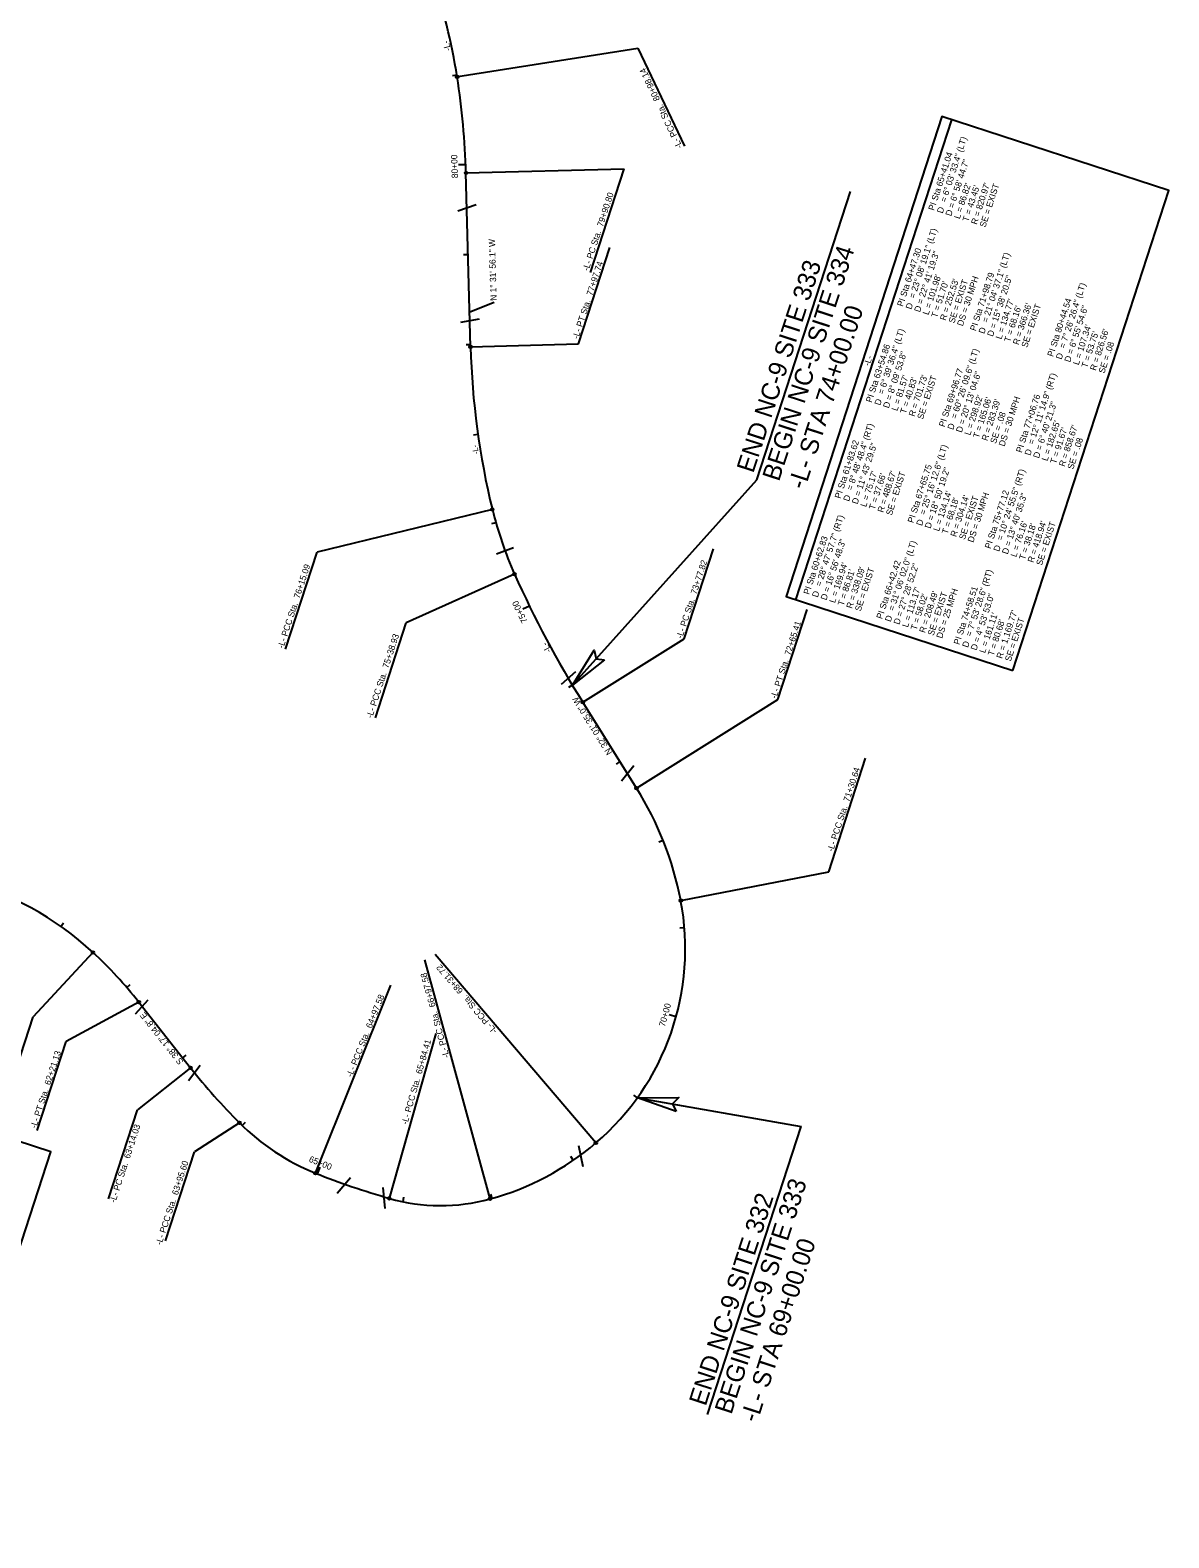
# Model space of a CAD drawing. Extents: x 1019959 to 1023888, y 635993 to 644996.
# Drawn here: x 1022623 to 1023888, y 639454 to 641128 of the extents above; entities that cross this region are included whole.
import ezdxf

# ---------------------------------------------------------------- set-up
doc = ezdxf.new("R2010")
doc.units = 0
for name, color, linetype in [('Cogo Default Point CELL', 7, 'Continuous'), ('COGO Default Point Elevation', 7, 'Continuous'), ('COGO Default Point Number', 7, 'Continuous'), ('Exist Other Culture Well CELL', 7, 'Continuous'), ('Exist Roads EOT', 7, 'Continuous'), ('Exist Structure Minor Pipes CMP 18 Inch Cogo Comment', 7, 'Continuous'), ('Exist Structure Minor Pipes CMP 18 Inch Cogo Number', 7, 'Continuous'), ('Exist Structure Minor Pipes CMP 24 Inch Cogo Number', 7, 'Continuous'), ('Exist Utilities Power Pole CELL', 7, 'Continuous'), ('Exist Utilities Power Pole Cogo Elevation', 7, 'Continuous'), ('Exist Utilities Power Pole Cogo Number', 7, 'Continuous')]:
    doc.layers.add(name, color=color, linetype=linetype)

msp = doc.modelspace()

# ---------------------------------------------------------------- linework, layer by layer
at = {"layer": 'COGO Default Point Elevation'}
for p, q in [((1023097.3, 641078.5), (1023092.3, 641077.7)), ((1023109.8, 640879), (1023104.8, 640878.9)), ((1023112.5, 640779.1), (1023107.5, 640778.9)), ((1023120.7, 640679.5), (1023115.7, 640678.8)), ((1023140.6, 640581.5), (1023135.8, 640580.2)), ((1023225.6, 640401.1), (1023221.3, 640398.5)), ((1023278.4, 640316.2), (1023274.2, 640313.5)), ((1023326.3, 640228.6), (1023321.7, 640226.7)), ((1022657.4, 640133.2), (1022660.3, 640137.3)), ((1023350.1, 640131.8), (1023345.1, 640131.4)), ((1022730.6, 640065.4), (1022734.4, 640068.7)), ((1022792.9, 639987.2), (1022796.8, 639990.3)), ((1023297.8, 639943), (1023293.8, 639945.9)), ((1022858.9, 639912.1), (1022862.4, 639915.7)), ((1023226.6, 639873.6), (1023223.8, 639877.7)), ((1023037.5, 639827.6), (1023038.5, 639832.5)), ((1023136.5, 639831.3), (1023135.1, 639836.1))]:
    msp.add_line(p, q, dxfattribs=at)
at = {"layer": 'COGO Default Point Number'}
for p, q in [((1023107.1, 640979), (1023099.1, 640978.7)), ((1023177.9, 640488.9), (1023170.7, 640485.4)), ((1023340.8, 640032.8), (1023333.1, 640034.9)), ((1022942.5, 639858.4), (1022945.4, 639865.9))]:
    msp.add_line(p, q, dxfattribs=at)
at = {"layer": 'Exist Other Culture Well CELL'}
for p, q in [((1023430.3, 640629.2), (1023534.3, 640949.2)), ((1023225.6, 640401.1), (1023430.3, 640629.2)), ((1023297.8, 639943), (1023479.7, 639911.2)), ((1023375.7, 639591.2), (1023479.7, 639911.2))]:
    msp.add_line(p, q, dxfattribs=at)
at = {"layer": 'Exist Roads EOT'}
for p, q in [((1023096.1, 641076.4), (1023298.4, 641108.3)), ((1023298.4, 641108.3), (1023350, 640999.5)), ((1023107.4, 640969.8), (1023283.1, 640974.5)), ((1023245.6, 640859.1), (1023283.1, 640974.5)), ((1023232.3, 640780), (1023267.1, 640886.9)), ((1023112.5, 640776.8), (1023232.3, 640780)), ((1023136.7, 640596.1), (1022942.1, 640548.6)), ((1022907.1, 640441), (1022942.1, 640548.6)), ((1023349.8, 640452.6), (1023382.2, 640552.4)), ((1023161.4, 640524.2), (1023041, 640470.3)), ((1023453.8, 640385), (1023486.3, 640485.1)), ((1023006.8, 640364.9), (1023041, 640470.3)), ((1023237.2, 640382.1), (1023349.8, 640452.6)), ((1023296.8, 640286.8), (1023453.8, 640385)), ((1023510.3, 640194), (1023551.2, 640319.9)), ((1023345.9, 640162.1), (1023510.3, 640194)), ((1022693.1, 640104.3), (1022626.6, 640032.7)), ((1023134.1, 639830.7), (1023061.8, 640096)), ((1023251.7, 639892.9), (1023073.1, 640101.9)), ((1022940.2, 639859.3), (1023024.1, 640067.9)), ((1022744.1, 640049.1), (1022663.3, 640005.5)), ((1022594.8, 639934.8), (1022626.6, 640032.7)), ((1023022.3, 639831.3), (1023074.3, 640014.3)), ((1022631.2, 639906.7), (1022663.3, 640005.5)), ((1022801.6, 639976.2), (1022742.5, 639929.5)), ((1022710.3, 639830.6), (1022742.5, 639929.5)), ((1022855.8, 639915.2), (1022806, 639882.8)), ((1022773.8, 639784), (1022806, 639882.8))]:
    msp.add_line(p, q, dxfattribs=at)
for centre in [(1023097.5, 641076.6), (1023107.4, 640969.8), (1023112.5, 640776.8), (1023136.7, 640596.1), (1023161.4, 640524.2), (1023237.2, 640382.1), (1023296.8, 640286.8), (1023345.9, 640162.1), (1022693.1, 640104.3), (1022744.1, 640049.1), (1022801.6, 639976.2), (1022855.8, 639915.2), (1023251.7, 639892.9), (1022940.2, 639859.3), (1023022.3, 639831.3), (1023134.1, 639830.7)]:
    msp.add_circle(centre, 1.5, dxfattribs=at)
at = {"layer": 'Exist Structure Minor Pipes CMP 18 Inch Cogo Comment'}
for points in [[(1023261.4, 640429.4), (1023225.6, 640401.1), (1023249.9, 640440.1), (1023252, 640430.5)], [(1023340.8, 639927.6), (1023297.8, 639943), (1023343.8, 639943.1), (1023336.7, 639936.2)]]:
    msp.add_lwpolyline(points, close=True, dxfattribs=at)
at = {"layer": 'Exist Structure Minor Pipes CMP 18 Inch Cogo Number'}
for p, q in [((1023112.5, 640776.8), (1023107.4, 640969.8)), ((1023296.8, 640286.8), (1023237.2, 640382.1)), ((1022744.1, 640049.1), (1022801.6, 639976.2))]:
    msp.add_line(p, q, dxfattribs=at)
for centre, radius, start, end in [((1022417.8, 640969.3), 688.2, 8.9729, 18.6571), ((1022281.1, 640947.7), 826.6, 1.5322, 8.9729), ((1023970.9, 640799.8), 858.7, 181.5322, 193.7197), ((1023543.7, 640695.5), 418.9, 193.7197, 204.1351), ((1024228.9, 641002.5), 1169.8, 204.1351, 212.0264), ((1022986.2, 640092.6), 366.4, 10.9494, 32.0264), ((1022463, 639856.6), 338.1, 47.0981, 75.8975), ((1023067.6, 640108.3), 283.4, 310.5134, 10.9494), ((1022360.5, 639746.3), 488.7, 38.2847, 47.0981), ((1023352.4, 640410.9), 701.7, 218.2847, 224.9448), ((1023034.5, 640093.6), 252.5, 224.9448, 248.0834), ((1023054.2, 640124.1), 304.1, 285.2433, 310.5134), ((1023246.7, 640621), 821, 248.0834, 254.1427), ((1023079.3, 640031.8), 208.5, 254.1427, 285.2433)]:
    msp.add_arc(centre, radius, start, end, dxfattribs=at)
at = {"layer": 'Exist Structure Minor Pipes CMP 24 Inch Cogo Number'}
for p, q in [((1023098.3, 640927.7), (1023118.8, 640934.7)), ((1023101.6, 640804.3), (1023122.6, 640807.9)), ((1023141.3, 640546.8), (1023160.3, 640553.8)), ((1023229.1, 640415.8), (1023213.2, 640401.8)), ((1023280.3, 640294.7), (1023293.9, 640311.8)), ((1022740.4, 640036.3), (1022754.4, 640051.8)), ((1022812.2, 639978.7), (1022799.2, 639961.6)), ((1023232.3, 639889.9), (1023237.3, 639866.7)), ((1022979.3, 639854.2), (1022964.3, 639836.7)), ((1023015.2, 639843.2), (1023017.3, 639820.1))]:
    msp.add_line(p, q, dxfattribs=at)
at = {"layer": 'Exist Utilities Power Pole CELL'}
for p, q in [((1023112.5, 640776.8), (1023107.4, 640969.8)), ((1023296.8, 640286.8), (1023237.2, 640382.1)), ((1022744.1, 640049.1), (1022801.6, 639976.2))]:
    msp.add_line(p, q, dxfattribs=at)
for centre, radius, start, end in [((1022417.8, 640969.3), 688.2, 8.9729, 18.6571), ((1022281.1, 640947.7), 826.6, 1.5322, 8.9729), ((1023970.9, 640799.8), 858.7, 181.5322, 193.7197), ((1023543.7, 640695.5), 418.9, 193.7197, 204.1351), ((1024228.9, 641002.5), 1169.8, 204.1351, 212.0264), ((1022986.2, 640092.6), 366.4, 10.9494, 32.0264), ((1022463, 639856.6), 338.1, 47.0981, 75.8975), ((1023067.6, 640108.3), 283.4, 310.5134, 10.9494), ((1022360.5, 639746.3), 488.7, 38.2847, 47.0981), ((1023352.4, 640410.9), 701.7, 218.2847, 224.9448), ((1023034.5, 640093.6), 252.5, 224.9448, 248.0834), ((1023054.2, 640124.1), 304.1, 285.2433, 310.5134), ((1023246.7, 640621), 821, 248.0834, 254.1427), ((1023079.3, 640031.8), 208.5, 254.1427, 285.2433)]:
    msp.add_arc(centre, radius, start, end, dxfattribs=at)
at = {"layer": 'Exist Utilities Power Pole Cogo Elevation'}
msp.add_line((1023473.7, 640495.9), (1023647, 641028.9), dxfattribs=at)
for points in [[(1023714.8, 640417.5), (1023888.1, 640950.5), (1023636.1, 641032.4), (1023462.9, 640499.4)], [(1022506.8, 639454.3), (1022646.2, 639883.1), (1022474.9, 639938.8), (1022335.5, 639510)]]:
    msp.add_lwpolyline(points, close=True, dxfattribs=at)
at = {"layer": 'Exist Utilities Power Pole Cogo Number'}
msp.add_line((1023138.7, 640826), (1023111.5, 640815.1), dxfattribs=at)

# ---------------------------------------------------------------- texts
at = {"layer": 'Cogo Default Point CELL'}
for s, rotation, p in [('80+00', 92.1701, (1023098.6, 640964.1)), ('75+00', 116.0421, (1023176.1, 640472)), ('70+00', 74.5371, (1023328.3, 640021.4)), ('65+00', 338.252, (1022932.3, 639872.2))]:
    msp.add_text(s, height=7, rotation=rotation, dxfattribs=at).set_placement(p)
at = {"layer": 'Exist Other Culture Well CELL'}
for s, p in [('BEGIN NC-9 SITE 334', (1023455, 640626.4)), ('END NC-9 SITE 333', (1023426.5, 640635.7)), ('-L- STA 74+00.00', (1023483.6, 640617.2)), ('BEGIN NC-9 SITE 333', (1023402.1, 639590.5)), ('END NC-9 SITE 332', (1023373.6, 639599.8)), ('-L- STA 69+00.00', (1023430.7, 639581.3))]:
    msp.add_text(s, height=20, rotation=71.9903, dxfattribs=at).set_placement(p)
at = {"layer": 'Exist Roads EOT'}
for s, rotation, p in [('-L- PCC Sta.  80+98.14', 115.343, (1023348, 640998.8)), ('-L- PC Sta.  79+90.80', 71.9903, (1023243.5, 640860.5)), ('-L- PT Sta.  77+97.74', 71.9903, (1023232.1, 640784.9)), ('-L- PCC Sta.  76+15.09', 71.9903, (1022904.5, 640441.3)), ('-L- PC Sta.  73+77.82', 71.9903, (1023347.5, 640452.3)), ('-L- PT Sta.  72+65.41', 71.9903, (1023452.1, 640385.6)), ('-L- PCC Sta.  75+38.93', 71.9903, (1023003.1, 640363.9)), ('-L- PCC Sta.  71+30.64', 71.9903, (1023515, 640215.6)), ('-L- PCC Sta.  66+97.58', 105.2433, (1023089.1, 639988.3)), ('-L- PCC Sta.  68+31.72', 130.5134, (1023142.5, 640017.6)), ('-L- PCC Sta.  64+97.58', 68.0834, (1022980.7, 639965.4)), ('-L- PT Sta.  62+21.13', 71.9903, (1022630, 639908.5)), ('-L- PCC Sta.  65+84.41', 74.1427, (1023042.2, 639912.7)), ('-L- PC Sta.  63+14.03', 71.9903, (1022717.9, 639825.8)), ('-L- PCC Sta.  63+95.60', 71.9903, (1022769.2, 639778.9))]:
    msp.add_text(s, height=7, rotation=rotation, dxfattribs=at).set_placement(p)
at = {"layer": 'Exist Utilities Power Pole Cogo Elevation'}
for s, rotation, p in [('= 6%%d 03\' 33.4" (LT)', 71.9892, (1023640.5, 640936.7)), ('PI Sta 65+41.04', 71.9892, (1023627.3, 640927.5)), ('D = 6%%d 58\' 44.7"', 71.9892, (1023646.3, 640921.3)), ("L = 86.82'", 71.9892, (1023655.8, 640918.2)), ("T = 43.45'", 71.9892, (1023665.3, 640915.1)), ("R = 820.97'", 71.9892, (1023674.8, 640912)), ('SE = EXIST', 71.9903, (1023684.3, 640908.9)), ('D', 71.9892, (1023636.8, 640924.4)), ('= 23%%d 08\' 19.1" (LT)', 71.9892, (1023605.8, 640830.1)), ('PI Sta 64+47.30', 71.9892, (1023592.6, 640820.9)), ('D = 22%%d 41\' 19.3"', 71.9892, (1023611.6, 640814.7)), ('= 21%%d 04\' 37.1" (LT)', 71.9892, (1023686.8, 640803.1)), ("L = 101.98'", 71.9892, (1023621.1, 640811.6)), ("T = 51.70'", 71.9892, (1023630.6, 640808.5)), ("R = 252.53'", 71.9892, (1023640.2, 640805.4)), ('SE = EXIST', 71.9903, (1023649.7, 640802.3)), ('DS = 30 MPH', 71.9892, (1023659.2, 640799.2)), ('PI Sta 71+98.79', 71.9892, (1023673.6, 640793.8)), ('D = 15%%d 38\' 20.5"', 71.9892, (1023692.6, 640787.6)), ('= 7%%d 26\' 26.4" (LT)', 71.9892, (1023772.6, 640774.5)), ("L = 134.77'", 71.9892, (1023702.1, 640784.6)), ('PI Sta 80+44.54', 71.9892, (1023759.4, 640765.2)), ('D', 71.9892, (1023602.1, 640817.8)), ("T = 68.16'", 71.9892, (1023711.6, 640781.5)), ("R = 366.36'", 71.9892, (1023721.2, 640778.4)), ('SE = EXIST', 71.9903, (1023730.7, 640775.3)), ('D = 6%%d 55\' 54.6"', 71.9892, (1023778.4, 640759.1)), ('D', 71.9892, (1023683.1, 640790.7)), ("L = 107.34'", 71.9892, (1023787.9, 640756)), ("R = 826.56'", 71.9892, (1023806.9, 640749.8)), ('PI Sta 63+54.86', 71.9892, (1023557.9, 640714.3)), ('= 6%%d 39\' 36.4" (LT)', 71.9892, (1023571.2, 640723.5)), ("T = 53.75'", 71.9892, (1023797.4, 640752.9)), ('SE = .08', 71.9892, (1023816.4, 640746.7)), ('-L-', 71.9903, (1023555.6, 640754.9)), ('D = 8%%d 09\' 53.8"', 71.9892, (1023577, 640708.1)), ('= 60%%d 26\' 09.6" (LT)', 71.9892, (1023652.2, 640696.4)), ('D', 71.9892, (1023768.9, 640762.2)), ("R = 701.73'", 71.9892, (1023605.5, 640698.8)), ('PI Sta 69+96.77', 71.9892, (1023639, 640687.2)), ('D = 20%%d 13\' 04.6"', 71.9892, (1023658, 640681)), ('= 12%%d 11\' 14.9" (RT)', 71.9892, (1023737.9, 640667.9)), ("L = 81.57'", 71.9892, (1023586.5, 640705)), ("T = 40.83'", 71.9892, (1023596, 640701.9)), ('SE = EXIST', 71.9903, (1023615, 640695.7)), ('D', 71.9892, (1023567.5, 640711.2)), ("L = 298.92'", 71.9892, (1023667.5, 640678)), ("T = 165.06'", 71.9892, (1023677, 640674.9)), ("R = 283.39'", 71.9892, (1023686.5, 640671.8)), ('DS = 30 MPH', 71.9892, (1023705.5, 640665.6)), ('PI Sta 77+06.76', 71.9892, (1023724.7, 640658.6)), ('D = 6%%d 40\' 21.3"', 71.9892, (1023743.7, 640652.5)), ('SE = .08', 71.9892, (1023696, 640668.7)), ('= 8%%d 48\' 48.4" (RT)', 71.9903, (1023536.5, 640616.9)), ('D', 71.9892, (1023648.5, 640684.1)), ("L = 182.65'", 71.9892, (1023753.2, 640649.4)), ("T = 91.67'", 71.9892, (1023762.7, 640646.3)), ("R = 858.67'", 71.9892, (1023772.3, 640643.2)), ('PI Sta 61+83.62', 71.9903, (1023523.3, 640607.7)), ('D = 11%%d 43\' 29.5"', 71.9903, (1023542.3, 640601.5)), ('= 25%%d 16\' 12.6" (LT)', 71.9892, (1023617.5, 640589.8)), ('D', 71.9892, (1023734.2, 640655.5)), ('SE = .08', 71.9892, (1023781.8, 640640.1)), ('PI Sta 67+65.75', 71.9892, (1023604.3, 640580.6)), ("L = 75.17'", 71.9903, (1023551.8, 640598.4)), ("T = 37.66'", 71.9903, (1023561.3, 640595.3)), ("R = 488.67'", 71.9903, (1023570.8, 640592.2)), ('SE = EXIST', 71.9903, (1023580.3, 640589.1)), ('D = 18%%d 50\' 19.2"', 71.9892, (1023623.3, 640574.4)), ('= 10%%d 24\' 55.5" (RT)', 71.9892, (1023703.2, 640561.3)), ('D', 71.9903, (1023532.8, 640604.6)), ("L = 134.14'", 71.9892, (1023632.8, 640571.4)), ("R = 304.14'", 71.9892, (1023651.8, 640565.2)), ('DS = 30 MPH', 71.9892, (1023670.9, 640559)), ('PI Sta 75+77.12', 71.9892, (1023690, 640552)), ('D = 13%%d 40\' 35.3"', 71.9892, (1023709.1, 640545.9)), ("T = 68.18'", 71.9892, (1023642.3, 640568.3)), ('SE = EXIST', 71.9903, (1023661.4, 640562.1)), ('= 28%%d 47\' 57.7" (RT)', 71.9903, (1023501.8, 640510.3)), ('D', 71.9892, (1023613.8, 640577.5)), ("L = 76.16'", 71.9892, (1023718.6, 640542.8)), ("T = 38.18'", 71.9892, (1023728.1, 640539.7)), ("R = 418.94'", 71.9892, (1023737.6, 640536.6)), ('SE = EXIST', 71.9903, (1023747.1, 640533.5)), ('PI Sta 60+62.83', 71.9903, (1023488.6, 640501.1)), ('D = 16%%d 56\' 48.3"', 71.9903, (1023507.7, 640494.9)), ('= 31%%d 06\' 02.0" (LT)', 71.9892, (1023582.8, 640483.2)), ('D', 71.9892, (1023699.6, 640548.9)), ("L = 169.94'", 71.9903, (1023517.2, 640491.8)), ("T = 86.81'", 71.9903, (1023526.7, 640488.7)), ("R = 338.09'", 71.9903, (1023536.2, 640485.6)), ('SE = EXIST', 71.9903, (1023545.7, 640482.5)), ('PI Sta 66+42.42', 71.9892, (1023569.6, 640474)), ('D = 27%%d 28\' 52.2"', 71.9892, (1023588.7, 640467.8)), ('= 7%%d 53\' 28.6" (RT)', 71.9892, (1023668.6, 640454.7)), ('D', 71.9903, (1023498.1, 640498)), ("L = 113.17'", 71.9892, (1023598.2, 640464.7)), ("T = 58.02'", 71.9892, (1023607.7, 640461.7)), ("R = 208.49'", 71.9892, (1023617.2, 640458.6)), ('SE = EXIST', 71.9903, (1023626.7, 640455.5)), ('DS = 25 MPH', 71.9892, (1023636.2, 640452.4)), ('PI Sta 74+58.51', 71.9892, (1023655.4, 640445.4)), ('D = 4%%d 53\' 53.0"', 71.9892, (1023674.4, 640439.2)), ('D', 71.9892, (1023579.1, 640470.9)), ("L = 161.11'", 71.9892, (1023683.9, 640436.2)), ("R = 1,169.77'", 71.9892, (1023702.9, 640430)), ("T = 80.68'", 71.9892, (1023693.4, 640433.1)), ('SE = EXIST', 71.9903, (1023712.4, 640426.9)), ('D', 71.9892, (1023664.9, 640442.3))]:
    msp.add_text(s, height=7, rotation=rotation, dxfattribs=at).set_placement(p)
at = {"layer": 'Exist Utilities Power Pole Cogo Number'}
for s, height, rotation, p in [('-L-', 7, 103.815, (1023090.7, 641106.2)), ('N 1%%d 31\' 56.1" W', 7, 91.5322, (1023141.5, 640827.9)), ('-L-', 6.3, 100.2976, (1023121.7, 640658.2)), ('-L-', 7, 118.4911, (1023202.5, 640439.4)), ('N 32%%d 01\' 35.0" W', 7, 122.0264, (1023270.2, 640326.3)), ('S 38%%d 17\' 04.8" E', 7, 128.2847, (1022794, 639983.2))]:
    msp.add_text(s, height=height, rotation=rotation, dxfattribs=at).set_placement(p)

doc.saveas('drawing.dxf')
